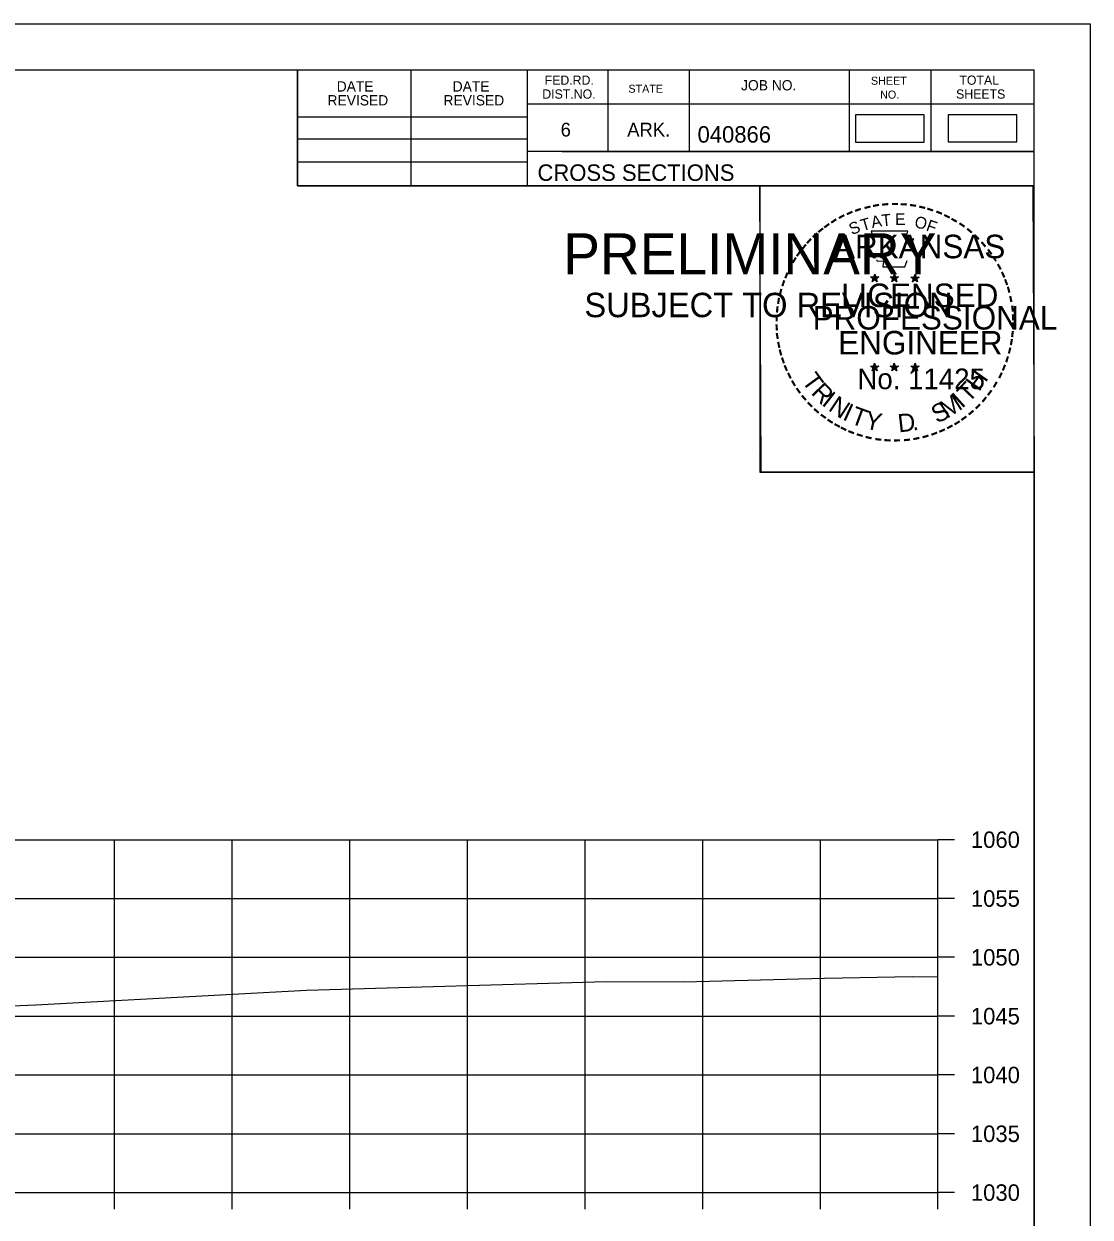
# Model space of a CAD drawing. Extents: x 1370565 to 1374448, y 301010 to 304637.
# Drawn here: x 1373441.1 to 1373531.7, y 303116.9 to 303218.4 of the extents above; entities that cross this region are included whole.
import ezdxf

# ---------------------------------------------------------------- set-up
doc = ezdxf.new("R2010")
doc.units = 0
for name, color, linetype in [('Default', 7, 'Continuous'), ('R_Axis', 7, 'Continuous'), ('R_Axis Annot', 7, 'Continuous'), ('R_Border', 7, 'Continuous'), ('R_Border PE', 7, 'Continuous'), ('R_Border Prem', 7, 'Continuous'), ('R_Drive', 7, 'Continuous'), ('R_Exist Surface', 7, 'Continuous'), ('R_Grid', 7, 'Continuous'), ('R_No Plot', 7, 'Continuous')]:
    doc.layers.add(name, color=color, linetype=linetype)

msp = doc.modelspace()

# ---------------------------------------------------------------- linework, layer by layer
at = {"layer": 'Default'}
msp.add_lwpolyline([(1373511.81, 303208.31), (1373517.64, 303208.31), (1373517.64, 303210.62), (1373511.81, 303210.62)], close=True, dxfattribs=at)
at = {"layer": 'R_Axis'}
for p, q in [((1373518.81, 303119), (1373518.81, 303149)), ((1373520.21, 303149), (1373518.81, 303149)), ((1373520.21, 303144), (1373518.81, 303144)), ((1373520.21, 303139), (1373518.81, 303139)), ((1373520.21, 303134), (1373518.81, 303134)), ((1373520.21, 303129), (1373518.81, 303129)), ((1373520.21, 303124), (1373518.81, 303124)), ((1373218.81, 303119), (1373518.81, 303119)), ((1373448.81, 303117.6), (1373448.81, 303119)), ((1373458.81, 303117.6), (1373458.81, 303119)), ((1373468.81, 303117.6), (1373468.81, 303119)), ((1373478.81, 303117.6), (1373478.81, 303119)), ((1373488.81, 303117.6), (1373488.81, 303119)), ((1373498.81, 303117.6), (1373498.81, 303119)), ((1373508.81, 303117.6), (1373508.81, 303119)), ((1373518.81, 303117.6), (1373518.81, 303119)), ((1373520.21, 303119), (1373518.81, 303119))]:
    msp.add_line(p, q, dxfattribs=at)
at = {"layer": 'R_Border'}
for p, q in [((1373210.81, 303214.46), (1373526.99, 303214.46)), ((1373464.35, 303204.58), (1373464.35, 303214.46)), ((1373474.03, 303204.58), (1373474.03, 303214.46)), ((1373483.89, 303214.46), (1373483.89, 303204.58)), ((1373490.73, 303214.46), (1373490.73, 303207.52)), ((1373497.67, 303214.46), (1373497.67, 303207.52)), ((1373511.25, 303214.46), (1373511.25, 303207.52)), ((1373518.19, 303214.46), (1373518.19, 303207.52)), ((1373526.99, 303009), (1373526.99, 303214.46)), ((1373526.99, 303211.52), (1373483.89, 303211.52)), ((1373526.99, 303211.54), (1373526.99, 303211.54)), ((1373464.35, 303210.44), (1373483.89, 303210.44)), ((1373464.35, 303208.58), (1373483.89, 303208.58)), ((1373526.99, 303207.52), (1373483.89, 303207.52)), ((1373486.85, 303207.52), (1373526.99, 303207.52)), ((1373464.35, 303206.64), (1373483.89, 303206.64)), ((1373526.99, 303204.58), (1373464.35, 303204.58))]:
    msp.add_line(p, q, dxfattribs=at)
at = {"layer": 'R_Border PE'}
for p, q in [((1373513.08, 303196.84), (1373513.43, 303196.73)), ((1373513.08, 303196.84), (1373513.33, 303196.79)), ((1373513.08, 303196.84), (1373513.32, 303196.72)), ((1373513.21, 303196.43), (1373513.43, 303196.73)), ((1373513.21, 303196.43), (1373513.34, 303196.67)), ((1373513.21, 303196.43), (1373513.43, 303196.65)), ((1373513.43, 303197.09), (1373513.39, 303196.84)), ((1373513.43, 303196.73), (1373513.43, 303197.09)), ((1373513.43, 303197.09), (1373513.48, 303196.84)), ((1373513.78, 303196.84), (1373513.43, 303196.73)), ((1373513.64, 303196.43), (1373513.43, 303196.73)), ((1373513.64, 303196.43), (1373513.43, 303196.64)), ((1373513.78, 303196.84), (1373513.49, 303196.79)), ((1373513.64, 303196.43), (1373513.5, 303196.72)), ((1373513.78, 303196.84), (1373513.57, 303196.74)), ((1373514.75, 303196.84), (1373515.1, 303196.73)), ((1373514.75, 303196.84), (1373515, 303196.79)), ((1373514.75, 303196.84), (1373514.99, 303196.72)), ((1373514.88, 303196.43), (1373515.1, 303196.73)), ((1373514.88, 303196.43), (1373515.01, 303196.67)), ((1373514.88, 303196.43), (1373515.1, 303196.65)), ((1373515.1, 303197.09), (1373515.06, 303196.84)), ((1373515.1, 303196.73), (1373515.1, 303197.09)), ((1373515.1, 303197.09), (1373515.15, 303196.84)), ((1373515.45, 303196.84), (1373515.1, 303196.73)), ((1373515.31, 303196.43), (1373515.1, 303196.73)), ((1373515.31, 303196.43), (1373515.1, 303196.64)), ((1373515.45, 303196.84), (1373515.16, 303196.79)), ((1373515.31, 303196.43), (1373515.17, 303196.72)), ((1373515.45, 303196.84), (1373515.24, 303196.74)), ((1373516.51, 303196.83), (1373516.86, 303196.71)), ((1373516.51, 303196.83), (1373516.77, 303196.78)), ((1373516.51, 303196.83), (1373516.75, 303196.7)), ((1373516.65, 303196.42), (1373516.86, 303196.71)), ((1373516.65, 303196.42), (1373516.77, 303196.66)), ((1373516.65, 303196.42), (1373516.86, 303196.63)), ((1373516.86, 303197.08), (1373516.82, 303196.83)), ((1373516.86, 303196.71), (1373516.86, 303197.08)), ((1373516.86, 303197.08), (1373516.91, 303196.83)), ((1373517.21, 303196.83), (1373516.86, 303196.71)), ((1373517.08, 303196.42), (1373516.86, 303196.71)), ((1373517.08, 303196.42), (1373516.86, 303196.63)), ((1373517.21, 303196.83), (1373516.92, 303196.78)), ((1373517.08, 303196.42), (1373516.94, 303196.71)), ((1373517.21, 303196.83), (1373517.01, 303196.72)), ((1373513.42, 303189.52), (1373513.38, 303189.27)), ((1373513.42, 303189.15), (1373513.42, 303189.52)), ((1373513.42, 303189.52), (1373513.47, 303189.27)), ((1373515.09, 303189.52), (1373515.05, 303189.27)), ((1373515.09, 303189.15), (1373515.09, 303189.52)), ((1373515.09, 303189.52), (1373515.14, 303189.27)), ((1373516.86, 303189.51), (1373516.82, 303189.26)), ((1373516.86, 303189.14), (1373516.86, 303189.51)), ((1373516.86, 303189.51), (1373516.91, 303189.26)), ((1373513.08, 303189.26), (1373513.42, 303189.15)), ((1373513.08, 303189.26), (1373513.33, 303189.22)), ((1373513.08, 303189.26), (1373513.31, 303189.14)), ((1373513.21, 303188.86), (1373513.42, 303189.15)), ((1373513.21, 303188.86), (1373513.33, 303189.1)), ((1373513.21, 303188.86), (1373513.42, 303189.07)), ((1373513.77, 303189.26), (1373513.42, 303189.15)), ((1373513.64, 303188.86), (1373513.42, 303189.15)), ((1373513.64, 303188.86), (1373513.42, 303189.07)), ((1373513.77, 303189.26), (1373513.49, 303189.22)), ((1373513.64, 303188.86), (1373513.5, 303189.15)), ((1373513.77, 303189.26), (1373513.57, 303189.16)), ((1373514.74, 303189.26), (1373515.09, 303189.15)), ((1373514.74, 303189.26), (1373515, 303189.22)), ((1373514.74, 303189.26), (1373514.98, 303189.14)), ((1373514.88, 303188.86), (1373515.09, 303189.15)), ((1373514.88, 303188.86), (1373515, 303189.1)), ((1373514.88, 303188.86), (1373515.09, 303189.07)), ((1373515.44, 303189.26), (1373515.09, 303189.15)), ((1373515.31, 303188.86), (1373515.09, 303189.15)), ((1373515.31, 303188.86), (1373515.09, 303189.07)), ((1373515.44, 303189.26), (1373515.15, 303189.22)), ((1373515.31, 303188.86), (1373515.17, 303189.15)), ((1373515.44, 303189.26), (1373515.24, 303189.16)), ((1373516.51, 303189.25), (1373516.86, 303189.14)), ((1373516.51, 303189.25), (1373516.76, 303189.21)), ((1373516.51, 303189.25), (1373516.75, 303189.13)), ((1373516.64, 303188.85), (1373516.86, 303189.14)), ((1373516.64, 303188.85), (1373516.77, 303189.09)), ((1373516.64, 303188.85), (1373516.86, 303189.06)), ((1373517.21, 303189.25), (1373516.86, 303189.14)), ((1373517.07, 303188.85), (1373516.86, 303189.14)), ((1373517.07, 303188.85), (1373516.86, 303189.06)), ((1373517.21, 303189.25), (1373516.92, 303189.21)), ((1373517.07, 303188.85), (1373516.94, 303189.14)), ((1373517.21, 303189.25), (1373517, 303189.15))]:
    msp.add_line(p, q, dxfattribs=at)
for points in [[(1373513.12, 303200.72), (1373513.39, 303199.89)], [(1373516.63, 303199.79), (1373516.77, 303200.08), (1373516.09, 303200.05), (1373516.24, 303200.72), (1373513.12, 303200.72)], [(1373513.61, 303198.29), (1373513.61, 303198.21), (1373514.18, 303198.19), (1373514.12, 303197.71), (1373515.99, 303197.71), (1373516.19, 303198.25)], [(1373513.43, 303197.09), (1373513.64, 303196.43), (1373513.08, 303196.84), (1373513.78, 303196.84), (1373513.21, 303196.43), (1373513.43, 303197.09)], [(1373515.1, 303197.09), (1373515.31, 303196.43), (1373514.75, 303196.84), (1373515.45, 303196.84), (1373514.88, 303196.43), (1373515.1, 303197.09)], [(1373516.86, 303197.08), (1373517.08, 303196.42), (1373516.51, 303196.83), (1373517.21, 303196.83), (1373516.65, 303196.42), (1373516.86, 303197.08)], [(1373513.42, 303189.52), (1373513.64, 303188.86), (1373513.08, 303189.26), (1373513.77, 303189.26), (1373513.21, 303188.86), (1373513.42, 303189.52)], [(1373515.09, 303189.52), (1373515.31, 303188.86), (1373514.74, 303189.26), (1373515.44, 303189.26), (1373514.88, 303188.86), (1373515.09, 303189.52)], [(1373516.86, 303189.51), (1373517.07, 303188.85), (1373516.51, 303189.25), (1373517.21, 303189.25), (1373516.64, 303188.85), (1373516.86, 303189.51)]]:
    msp.add_lwpolyline(points, dxfattribs=at)
for centre, radius in [((1373513.43, 303196.73), 0.172), ((1373513.43, 303196.73), 0.145), ((1373513.43, 303196.73), 0.116), ((1373513.43, 303196.73), 0.0991), ((1373513.43, 303196.73), 0.0747), ((1373513.43, 303196.73), 0.0495), ((1373513.43, 303196.73), 0.0296), ((1373515.1, 303196.73), 0.172), ((1373515.1, 303196.73), 0.145), ((1373515.1, 303196.73), 0.116), ((1373515.1, 303196.73), 0.0991), ((1373515.1, 303196.73), 0.0747), ((1373515.1, 303196.73), 0.0495), ((1373515.1, 303196.73), 0.0296), ((1373516.86, 303196.71), 0.172), ((1373516.86, 303196.71), 0.145), ((1373516.86, 303196.71), 0.116), ((1373516.86, 303196.71), 0.0991), ((1373516.86, 303196.71), 0.0747), ((1373516.86, 303196.71), 0.0495), ((1373516.86, 303196.71), 0.0296), ((1373513.42, 303189.15), 0.172), ((1373513.42, 303189.15), 0.145), ((1373513.42, 303189.15), 0.116), ((1373513.42, 303189.15), 0.0991), ((1373513.42, 303189.15), 0.0747), ((1373513.42, 303189.15), 0.0495), ((1373513.42, 303189.15), 0.0296), ((1373515.09, 303189.15), 0.172), ((1373515.09, 303189.15), 0.145), ((1373515.09, 303189.15), 0.116), ((1373515.09, 303189.15), 0.0991), ((1373515.09, 303189.15), 0.0747), ((1373515.09, 303189.15), 0.0495), ((1373515.09, 303189.15), 0.0296), ((1373516.86, 303189.14), 0.172), ((1373516.86, 303189.14), 0.145), ((1373516.86, 303189.14), 0.116), ((1373516.86, 303189.14), 0.0991), ((1373516.86, 303189.14), 0.0747), ((1373516.86, 303189.14), 0.0495), ((1373516.86, 303189.14), 0.0296)]:
    msp.add_circle(centre, radius, dxfattribs=at)
at = {"layer": 'R_Drive'}
msp.add_lwpolyline([(1373519.68, 303208.32), (1373525.51, 303208.32), (1373525.51, 303210.63), (1373519.68, 303210.63)], close=True, dxfattribs=at)
at = {"layer": 'R_Exist Surface'}
msp.add_lwpolyline([(1373302.68, 303133.71), (1373328.59, 303133.89), (1373360.04, 303134.14), (1373368.35, 303132.82), (1373373.07, 303132.03), (1373380.91, 303133.09), (1373390.62, 303134.43), (1373395.51, 303134.52), (1373400.91, 303134.61), (1373407.05, 303134.46), (1373410.67, 303134.37), (1373411.77, 303134.24), (1373424.7, 303134.54), (1373436.57, 303134.69), (1373438.65, 303134.81), (1373442.1, 303134.96), (1373465.12, 303136.2), (1373490.59, 303136.94), (1373497.19, 303136.91), (1373509.16, 303137.23), (1373515.15, 303137.34), (1373516.66, 303137.37), (1373518.81, 303137.34)], dxfattribs=at)
at = {"layer": 'R_Grid'}
for p, q in [((1373218.81, 303149), (1373518.81, 303149)), ((1373448.81, 303119), (1373448.81, 303149)), ((1373458.81, 303119), (1373458.81, 303149)), ((1373468.81, 303119), (1373468.81, 303149)), ((1373478.81, 303119), (1373478.81, 303149)), ((1373488.81, 303119), (1373488.81, 303149)), ((1373498.81, 303119), (1373498.81, 303149)), ((1373508.81, 303119), (1373508.81, 303149)), ((1373518.81, 303119), (1373518.81, 303149)), ((1373218.81, 303144), (1373518.81, 303144)), ((1373218.81, 303139), (1373518.81, 303139)), ((1373218.81, 303134), (1373518.81, 303134)), ((1373218.81, 303129), (1373518.81, 303129)), ((1373218.81, 303124), (1373518.81, 303124)), ((1373218.81, 303119), (1373518.81, 303119))]:
    msp.add_line(p, q, dxfattribs=at)
at = {"layer": 'R_No Plot'}
for p, q in [((1373198.41, 303218.36), (1373531.75, 303218.36)), ((1373503.03, 303182.13), (1373503.03, 303182.13))]:
    msp.add_line(p, q, dxfattribs=at)
for points in [[(1373198.41, 303218.36), (1373531.75, 303218.36), (1373531.75, 303005.02), (1373198.41, 303005.02)], [(1373444.73, 303214.46), (1373464.35, 303214.46), (1373464.35, 303204.58), (1373480.47, 303204.58), (1373503.67, 303204.58), (1373503.67, 303180.25), (1373526.99, 303180.25), (1373526.99, 303009), (1373210.81, 303009), (1373210.81, 303214.46)], [(1373503.67, 303204.58), (1373526.87, 303204.58), (1373526.99, 303180.25), (1373503.79, 303180.25)]]:
    msp.add_lwpolyline(points, close=True, dxfattribs=at)

# ---------------------------------------------------------------- texts
at = {"layer": 'R_Axis Annot'}
for s, p in [('1060', (1373521.61, 303148.3)), ('1055', (1373521.61, 303143.3)), ('1050', (1373521.61, 303138.3)), ('1045', (1373521.61, 303133.3)), ('1040', (1373521.61, 303128.3)), ('1035', (1373521.61, 303123.3)), ('1030', (1373521.61, 303118.3))]:
    msp.add_text(s, height=1.4, dxfattribs=at).set_placement(p)
at = {"layer": 'R_Border'}
for s, height, p in [('FED.RD.', 0.782, (1373485.37, 303213.18)), ('SHEET', 0.684, (1373513.11, 303213.18)), ('TOTAL', 0.782, (1373520.63, 303213.18)), ('DATE', 0.879, (1373467.69, 303212.6)), ('DATE', 0.879, (1373477.55, 303212.6)), ('DIST.NO.', 0.782, (1373485.17, 303212)), ('STATE', 0.684, (1373492.49, 303212.5)), ('JOB NO.', 0.879, (1373502.07, 303212.7)), ('SHEETS', 0.782, (1373520.35, 303212)), ('REVISED', 0.879, (1373466.91, 303211.42)), ('REVISED', 0.879, (1373476.77, 303211.42)), ('NO.', 0.684, (1373513.89, 303212)), ('6', 1.17, (1373486.73, 303208.78)), ('ARK.', 1.172, (1373492.39, 303208.78)), ('040866', 1.4, (1373498.37, 303208.26)), ('CROSS SECTIONS', 1.4, (1373484.76, 303205.01))]:
    msp.add_text(s, height=height, rotation=360, dxfattribs=at).set_placement(p)
at = {"layer": 'R_Border PE'}
for s, height, rotation, p in [('-', 1.6, 19.1761, (1373511.87, 303201.84)), ('-', 1.6, 13.6301, (1373512.62, 303202.08)), ('-', 1.6, 10.2193, (1373513.3, 303202.25)), ('-', 1.6, 5.8968, (1373514.03, 303202.36)), ('-', 1.6, 0.1862, (1373514.8, 303202.43)), ('-', 1.6, 357.743, (1373515.52, 303202.41)), ('-', 1.6, 352.1617, (1373516.26, 303202.36)), ('-', 1.6, 347.2049, (1373516.98, 303202.24)), ('-', 1.6, 342.3362, (1373517.62, 303202.09)), ('-', 1.6, 34.0636, (1373510, 303200.89)), ('-', 1.6, 28.7918, (1373510.6, 303201.26)), ('-', 1.6, 24.3072, (1373511.23, 303201.57)), ('T', 1, 16.4036, (1373512.39, 303200.72)), ('A', 1, 11.2132, (1373513.22, 303200.98)), ('T', 1, 6.0228, (1373514.06, 303201.14)), ('E', 1, 0.8323, (1373515.17, 303201.25)), ('O', 1, 350.4515, (1373516.77, 303201.04)), ('F', 1, 340.0707, (1373517.73, 303200.81)), ('-', 1.6, 337.8551, (1373518.35, 303201.87)), ('-', 1.6, 334.1211, (1373518.98, 303201.6)), ('-', 1.6, 329.6409, (1373519.56, 303201.31)), ('-', 1.6, 42.9622, (1373508.52, 303199.7)), ('-', 1.6, 38.9507, (1373508.95, 303200.11)), ('-', 1.6, 36.2317, (1373509.43, 303200.49)), ('S', 1, 21.594, (1373511.48, 303200.39)), ('-', 1.6, 325.8627, (1373520.21, 303200.95)), ('-', 1.6, 320.5297, (1373520.82, 303200.53)), ('-', 1.6, 50.6142, (1373507.67, 303198.73)), ('-', 1.6, 48.423, (1373508.07, 303199.22)), ('ARKANSAS', 2, 360, (1373509.97, 303198.43)), ('-', 1.6, 315.5786, (1373521.42, 303200.04)), ('-', 1.6, 309.8797, (1373521.98, 303199.49)), ('-', 1.6, 58.0706, (1373506.93, 303197.64)), ('-', 1.6, 54.2325, (1373507.25, 303198.17)), ('-', 1.6, 306.6522, (1373522.51, 303198.89)), ('-', 1.4, 303.6753, (1373523, 303198.32)), ('-', 1.6, 62.8713, (1373506.62, 303197.02)), ('-', 1.6, 299.6684, (1373523.31, 303197.71)), ('-', 1.6, 72.3945, (1373506.14, 303195.78)), ('-', 1.6, 67.7743, (1373506.36, 303196.41)), ('DWB', 0.01, 360, (1373513.42, 303196.72)), ('DWB', 0.01, 360, (1373515.09, 303196.72)), ('DWB', 0.01, 360, (1373516.85, 303196.71)), ('-', 1.6, 294.6628, (1373523.64, 303197.1)), ('-', 1.6, 290.5728, (1373523.9, 303196.52)), ('-', 1.6, 75.461, (1373505.94, 303195.07)), ('LICENSED', 2, 360, (1373510.57, 303194.28)), ('-', 1.6, 285.1233, (1373524.13, 303195.94)), ('-', 1.6, 81.2013, (1373505.81, 303194.36)), ('-', 1.6, 280.5493, (1373524.33, 303195.2)), ('-', 1.6, 89.0622, (1373505.71, 303192.96)), ('-', 1.6, 85.1863, (1373505.73, 303193.67)), ('PROFESSIONAL', 2, 360, (1373508.15, 303192.37)), ('-', 1.6, 276.5962, (1373524.49, 303194.43)), ('-', 1.6, 274.3301, (1373524.55, 303193.71)), ('-', 1.6, 94.1959, (1373505.74, 303192.24)), ('-', 1.6, 269.9407, (1373524.59, 303193.08)), ('-', 1.6, 98.9479, (1373505.81, 303191.57)), ('ENGINEER', 2, 360, (1373510.33, 303190.25)), ('-', 1.6, 260.9953, (1373524.5, 303191.76)), ('-', 1.6, 263.5172, (1373524.57, 303192.41)), ('-', 1.6, 101.7149, (1373505.95, 303190.84)), ('-', 1.6, 105.4578, (1373506.11, 303190.24)), ('-', 1.6, 255.7626, (1373524.39, 303191.08)), ('-', 1.6, 109.0874, (1373506.33, 303189.61)), ('-', 1.6, 252.8681, (1373524.2, 303190.36)), ('-', 1.6, 114.0643, (1373506.58, 303189.02)), ('-', 1.6, 115.7289, (1373506.89, 303188.4)), ('T', 1.54, 306.0406, (1373507.18, 303187.99)), ('No. 11425', 1.757, 360, (1373511.96, 303187.3)), ('DWB', 0.01, 360, (1373513.41, 303189.15)), ('DWB', 0.01, 360, (1373515.08, 303189.15)), ('DWB', 0.01, 360, (1373516.85, 303189.14)), ('H', 1.54, 54.6088, (1373522.3, 303187.03)), ('-', 1.6, 244.6197, (1373523.72, 303189.06)), ('-', 1.6, 247.8887, (1373523.98, 303189.69)), ('-', 1.6, 120.4471, (1373507.24, 303187.81)), ('-', 1.6, 125.8934, (1373507.65, 303187.25)), ('R', 1.54, 314.005, (1373507.95, 303186.94)), ('T', 1.54, 46.6444, (1373521.41, 303186.08)), ('-', 1.6, 239.0712, (1373523.33, 303188.31)), ('-', 1.6, 130.7181, (1373508.11, 303186.7)), ('I', 1.54, 321.9694, (1373508.85, 303186.01)), ('N', 1.54, 326.5002, (1373509.41, 303185.54)), ('M', 1.54, 32.6563, (1373519.57, 303184.76)), ('I', 1.54, 42.1136, (1373520.85, 303185.61)), ('-', 1.6, 231.2538, (1373522.49, 303187.09)), ('-', 1.6, 233.8452, (1373522.92, 303187.65)), ('-', 1.6, 134.2238, (1373508.62, 303186.16)), ('-', 1.6, 138.9338, (1373509.15, 303185.69)), ('I', 1.54, 335.3603, (1373510.62, 303184.75)), ('T', 1.54, 339.8912, (1373511.28, 303184.43)), ('Y', 1.54, 347.8556, (1373512.5, 303183.98)), ('S', 1.54, 26.9312, (1373518.73, 303184.35)), ('-', 1.6, 221.0851, (1373521.49, 303186.01)), ('-', 1.6, 225.7653, (1373522.01, 303186.52)), ('-', 1.6, 144.6463, (1373509.71, 303185.29)), ('-', 1.6, 148.0898, (1373510.27, 303184.91)), ('-', 1.6, 151.5704, (1373510.85, 303184.59)), ('D', 1.54, 6.3969, (1373515.48, 303183.62)), ('-', 1.6, 212.2491, (1373520.41, 303185.15)), ('-', 1.6, 215.7363, (1373520.94, 303185.54)), ('-', 1.6, 154.6002, (1373511.37, 303184.34)), ('-', 1.6, 158.5612, (1373511.99, 303184.09)), ('-', 1.6, 162.7983, (1373512.68, 303183.88)), ('-', 1.6, 167.5555, (1373513.39, 303183.71)), ('.', 1.54, 13.7642, (1373516.68, 303183.75)), ('-', 1.6, 195.4743, (1373517.93, 303183.97)), ('-', 1.6, 200.7184, (1373518.61, 303184.22)), ('-', 1.6, 204.2516, (1373519.23, 303184.49)), ('-', 1.6, 207.3568, (1373519.85, 303184.81)), ('-', 1.6, 173.1155, (1373514.17, 303183.6)), ('-', 1.6, 176.5183, (1373514.91, 303183.55)), ('-', 1.6, 181.5918, (1373515.66, 303183.57)), ('-', 1.6, 185.8167, (1373516.47, 303183.64)), ('-', 1.6, 191.2858, (1373517.2, 303183.78))]:
    msp.add_text(s, height=height, rotation=rotation, dxfattribs=at).set_placement(p)
at = {"layer": 'R_Border Prem'}
for s, height, p in [('PRELIMINARY', 3.5, (1373486.95, 303197.05)), ('DWB', 0.01, (1373487.69, 303198.89)), ('SUBJECT TO REVISION', 2.0751, (1373488.75, 303193.42))]:
    msp.add_text(s, height=height, rotation=360, dxfattribs=at).set_placement(p)

doc.saveas('drawing.dxf')
